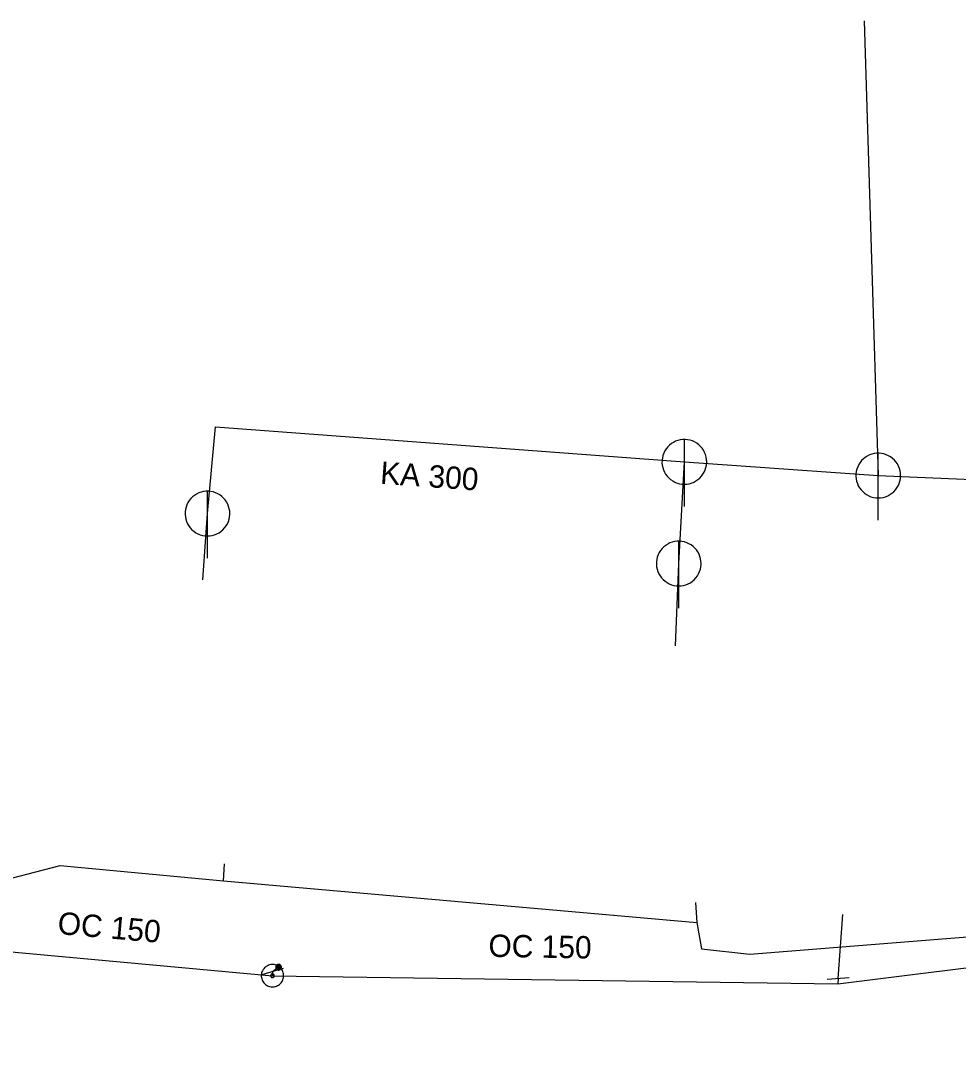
# Model space of a CAD drawing. Extents: x -759784 to -759434, y -974861 to -974639.
# Drawn here: x -759531.42 to -759489.52, y -974742.26 to -974695.97 of the extents above; entities that cross this region are included whole.
import ezdxf

# ---------------------------------------------------------------- set-up
doc = ezdxf.new("R2010")
doc.units = 0
for name, color, linetype in [('IS_CETIN_sdělovací kabel_podzemní', 7, 'Continuous'), ('IS_popis_ScVK', 7, 'Continuous'), ('IS_ScVK_Kanal', 7, 'Continuous'), ('IS_ScVK_Vodovod', 7, 'Continuous')]:
    doc.layers.add(name, color=color, linetype=linetype)

msp = doc.modelspace()

# ---------------------------------------------------------------- linework, layer by layer
at = {"layer": 'IS_CETIN_sdělovací kabel_podzemní'}
for points in [[(-759544.45, -974733.8), (-759533, -974734.6), (-759529.66, -974733.73), (-759522.36, -974734.42)], [(-759522.36, -974734.42), (-759522.31, -974733.66)], [(-759522.36, -974734.42), (-759501.2, -974736.28)], [(-759501.27, -974735.38), (-759501.2, -974736.28)], [(-759501.2, -974736.28), (-759500.99, -974737.45), (-759498.83, -974737.7), (-759486.31, -974736.7), (-759484.66, -974737.9), (-759478.97, -974736.71), (-759474.26, -974737.04), (-759472.35, -974737.88), (-759470.97, -974738.53), (-759469.61, -974739.15), (-759466.38, -974739.73), (-759464.12, -974740.75), (-759461.22, -974742.26)]]:
    msp.add_lwpolyline(points, dxfattribs=at)
at = {"layer": 'IS_ScVK_Kanal'}
for points in [[(-759493.728, -974695.967), (-759493.097, -974716.3)], [(-759523.077, -974718), (-759522.715, -974714.129)], [(-759522.715, -974714.129), (-759501.763, -974715.688)], [(-759500.763, -974715.688), (-759500.768, -974715.579), (-759500.786, -974715.471), (-759500.816, -974715.365), (-759500.856, -974715.264), (-759500.908, -974715.167), (-759500.97, -974715.077), (-759501.042, -974714.994), (-759501.122, -974714.92), (-759501.21, -974714.854), (-759501.304, -974714.799), (-759501.404, -974714.754), (-759501.509, -974714.721), (-759501.616, -974714.699), (-759501.725, -974714.689), (-759501.835, -974714.691), (-759501.943, -974714.705), (-759502.05, -974714.73), (-759502.153, -974714.767), (-759502.251, -974714.816), (-759502.343, -974714.874), (-759502.429, -974714.943), (-759502.506, -974715.02), (-759502.575, -974715.106), (-759502.634, -974715.198), (-759502.682, -974715.296), (-759502.719, -974715.399), (-759502.745, -974715.506), (-759502.759, -974715.614), (-759502.762, -974715.724), (-759502.752, -974715.833), (-759502.731, -974715.94), (-759502.697, -974716.044), (-759502.653, -974716.144), (-759502.598, -974716.239), (-759502.532, -974716.327), (-759502.458, -974716.407), (-759502.375, -974716.479), (-759502.285, -974716.541), (-759502.189, -974716.593), (-759502.087, -974716.634), (-759501.982, -974716.664), (-759501.874, -974716.682), (-759501.764, -974716.688), (-759501.655, -974716.682), (-759501.547, -974716.664), (-759501.442, -974716.635), (-759501.34, -974716.594), (-759501.243, -974716.542), (-759501.153, -974716.48), (-759501.07, -974716.409), (-759500.995, -974716.329), (-759500.93, -974716.241), (-759500.874, -974716.147), (-759500.83, -974716.047), (-759500.796, -974715.943), (-759500.774, -974715.835), (-759500.764, -974715.726), (-759500.763, -974715.688)], [(-759501.763, -974717.688), (-759501.762, -974714.688)], [(-759492.097, -974716.3), (-759492.102, -974716.191), (-759492.12, -974716.083), (-759492.15, -974715.977), (-759492.19, -974715.876), (-759492.242, -974715.779), (-759492.304, -974715.689), (-759492.376, -974715.606), (-759492.456, -974715.532), (-759492.544, -974715.466), (-759492.638, -974715.411), (-759492.738, -974715.366), (-759492.843, -974715.333), (-759492.95, -974715.311), (-759493.059, -974715.301), (-759493.169, -974715.303), (-759493.277, -974715.317), (-759493.384, -974715.342), (-759493.487, -974715.379), (-759493.585, -974715.428), (-759493.677, -974715.486), (-759493.763, -974715.555), (-759493.84, -974715.632), (-759493.909, -974715.718), (-759493.968, -974715.81), (-759494.016, -974715.908), (-759494.053, -974716.011), (-759494.079, -974716.118), (-759494.093, -974716.226), (-759494.096, -974716.336), (-759494.086, -974716.445), (-759494.065, -974716.552), (-759494.031, -974716.656), (-759493.987, -974716.756), (-759493.932, -974716.851), (-759493.866, -974716.939), (-759493.792, -974717.019), (-759493.709, -974717.091), (-759493.619, -974717.153), (-759493.523, -974717.205), (-759493.421, -974717.246), (-759493.316, -974717.276), (-759493.208, -974717.294), (-759493.098, -974717.3), (-759492.989, -974717.294), (-759492.881, -974717.276), (-759492.776, -974717.247), (-759492.674, -974717.206), (-759492.577, -974717.154), (-759492.487, -974717.092), (-759492.404, -974717.021), (-759492.329, -974716.941), (-759492.264, -974716.853), (-759492.208, -974716.759), (-759492.164, -974716.659), (-759492.13, -974716.555), (-759492.108, -974716.447), (-759492.098, -974716.338), (-759492.097, -974716.3)], [(-759493.097, -974718.3), (-759493.096, -974715.3)], [(-759502.016, -974720.235), (-759501.763, -974715.688)], [(-759501.763, -974715.688), (-759493.097, -974716.3)], [(-759493.097, -974716.3), (-759477.359, -974716.961)], [(-759522.077, -974718), (-759522.082, -974717.891), (-759522.1, -974717.783), (-759522.13, -974717.677), (-759522.17, -974717.576), (-759522.222, -974717.479), (-759522.284, -974717.389), (-759522.356, -974717.306), (-759522.436, -974717.232), (-759522.524, -974717.166), (-759522.618, -974717.111), (-759522.718, -974717.066), (-759522.823, -974717.033), (-759522.93, -974717.011), (-759523.039, -974717.001), (-759523.149, -974717.003), (-759523.257, -974717.017), (-759523.364, -974717.042), (-759523.467, -974717.079), (-759523.565, -974717.128), (-759523.657, -974717.186), (-759523.743, -974717.255), (-759523.82, -974717.332), (-759523.889, -974717.418), (-759523.948, -974717.51), (-759523.996, -974717.608), (-759524.033, -974717.711), (-759524.059, -974717.818), (-759524.073, -974717.926), (-759524.076, -974718.036), (-759524.066, -974718.145), (-759524.045, -974718.252), (-759524.011, -974718.356), (-759523.967, -974718.456), (-759523.912, -974718.551), (-759523.846, -974718.639), (-759523.772, -974718.719), (-759523.689, -974718.791), (-759523.599, -974718.853), (-759523.503, -974718.905), (-759523.401, -974718.946), (-759523.296, -974718.976), (-759523.188, -974718.994), (-759523.078, -974719), (-759522.969, -974718.994), (-759522.861, -974718.976), (-759522.756, -974718.947), (-759522.654, -974718.906), (-759522.557, -974718.854), (-759522.467, -974718.792), (-759522.384, -974718.721), (-759522.309, -974718.641), (-759522.244, -974718.553), (-759522.188, -974718.459), (-759522.144, -974718.359), (-759522.11, -974718.255), (-759522.088, -974718.147), (-759522.078, -974718.038), (-759522.077, -974718)], [(-759523.077, -974720), (-759523.076, -974717)], [(-759523.28, -974720.963), (-759523.077, -974718)], [(-759501.015, -974720.234), (-759501.02, -974720.125), (-759501.038, -974720.017), (-759501.068, -974719.911), (-759501.108, -974719.81), (-759501.16, -974719.713), (-759501.222, -974719.623), (-759501.294, -974719.54), (-759501.374, -974719.466), (-759501.462, -974719.4), (-759501.556, -974719.345), (-759501.656, -974719.3), (-759501.761, -974719.267), (-759501.868, -974719.245), (-759501.977, -974719.235), (-759502.087, -974719.237), (-759502.195, -974719.251), (-759502.302, -974719.276), (-759502.405, -974719.313), (-759502.503, -974719.362), (-759502.595, -974719.42), (-759502.681, -974719.489), (-759502.758, -974719.566), (-759502.827, -974719.652), (-759502.886, -974719.744), (-759502.934, -974719.842), (-759502.971, -974719.945), (-759502.997, -974720.052), (-759503.011, -974720.16), (-759503.014, -974720.27), (-759503.004, -974720.379), (-759502.983, -974720.486), (-759502.949, -974720.59), (-759502.905, -974720.69), (-759502.85, -974720.785), (-759502.784, -974720.873), (-759502.71, -974720.953), (-759502.627, -974721.025), (-759502.537, -974721.087), (-759502.441, -974721.139), (-759502.339, -974721.18), (-759502.234, -974721.21), (-759502.126, -974721.228), (-759502.016, -974721.234), (-759501.907, -974721.228), (-759501.799, -974721.21), (-759501.694, -974721.181), (-759501.592, -974721.14), (-759501.495, -974721.088), (-759501.405, -974721.026), (-759501.322, -974720.955), (-759501.247, -974720.875), (-759501.182, -974720.787), (-759501.126, -974720.693), (-759501.082, -974720.593), (-759501.048, -974720.489), (-759501.026, -974720.381), (-759501.016, -974720.272), (-759501.015, -974720.234)], [(-759502.015, -974722.234), (-759502.014, -974719.234)], [(-759502.163, -974723.919), (-759502.016, -974720.235)], [(-759519.899, -974738.278), (-759520.168, -974738.478)], [(-759520.168, -974738.478), (-759520.172, -974738.658)], [(-759494.888, -974738.788), (-759494.905, -974739.024)]]:
    msp.add_lwpolyline(points, dxfattribs=at)
at = {"layer": 'IS_ScVK_Vodovod'}
for points in [[(-759494.888, -974738.788), (-759494.686, -974735.919)], [(-759520.172, -974738.658), (-759494.905, -974739.024), (-759476.881, -974736.765), (-759471.711, -974737.208)], [(-759533.638, -974737.429), (-759520.172, -974738.658)], [(-759519.672, -974738.681), (-759519.673, -974738.629), (-759519.678, -974738.577), (-759519.69, -974738.526), (-759519.705, -974738.476), (-759519.727, -974738.428), (-759519.754, -974738.383), (-759519.785, -974738.341), (-759519.82, -974738.303), (-759519.859, -974738.268), (-759519.901, -974738.237), (-759519.947, -974738.211), (-759519.995, -974738.19), (-759520.044, -974738.174), (-759520.096, -974738.164), (-759520.148, -974738.158), (-759520.2, -974738.159), (-759520.252, -974738.164), (-759520.304, -974738.176), (-759520.353, -974738.191), (-759520.401, -974738.213), (-759520.446, -974738.24), (-759520.489, -974738.271), (-759520.527, -974738.306), (-759520.562, -974738.345), (-759520.592, -974738.387), (-759520.618, -974738.433), (-759520.64, -974738.481), (-759520.655, -974738.53), (-759520.665, -974738.582), (-759520.671, -974738.634), (-759520.67, -974738.686), (-759520.665, -974738.738), (-759520.654, -974738.79), (-759520.638, -974738.839), (-759520.616, -974738.887), (-759520.59, -974738.932), (-759520.559, -974738.975), (-759520.524, -974739.013), (-759520.484, -974739.048), (-759520.442, -974739.078), (-759520.396, -974739.104), (-759520.349, -974739.126), (-759520.299, -974739.141), (-759520.247, -974739.151), (-759520.195, -974739.157), (-759520.143, -974739.156), (-759520.091, -974739.151), (-759520.04, -974739.14), (-759519.99, -974739.124), (-759519.942, -974739.102), (-759519.897, -974739.076), (-759519.855, -974739.045), (-759519.817, -974739.01), (-759519.782, -974738.97), (-759519.751, -974738.928), (-759519.725, -974738.882), (-759519.704, -974738.835), (-759519.688, -974738.785), (-759519.678, -974738.733), (-759519.672, -974738.681)], [(-759519.688, -974738.336), (-759520.647, -974738.618)], [(-759520.025, -974738.278), (-759520.025, -974738.291), (-759520.022, -974738.304), (-759520.02, -974738.317), (-759520.015, -974738.329), (-759520.009, -974738.341), (-759520.002, -974738.352), (-759519.994, -974738.362), (-759519.983, -974738.372), (-759519.973, -974738.38), (-759519.963, -974738.387), (-759519.951, -974738.393), (-759519.939, -974738.398), (-759519.926, -974738.401), (-759519.913, -974738.403), (-759519.9, -974738.405), (-759519.887, -974738.404), (-759519.874, -974738.402), (-759519.861, -974738.399), (-759519.848, -974738.394), (-759519.837, -974738.388), (-759519.826, -974738.381), (-759519.816, -974738.373), (-759519.806, -974738.363), (-759519.798, -974738.353), (-759519.791, -974738.342), (-759519.785, -974738.33), (-759519.78, -974738.318), (-759519.777, -974738.305), (-759519.775, -974738.292), (-759519.772, -974738.279), (-759519.774, -974738.266), (-759519.776, -974738.253), (-759519.779, -974738.24), (-759519.784, -974738.228), (-759519.789, -974738.216), (-759519.797, -974738.205), (-759519.804, -974738.195), (-759519.815, -974738.185), (-759519.825, -974738.177), (-759519.836, -974738.17), (-759519.848, -974738.164), (-759519.86, -974738.159), (-759519.873, -974738.156), (-759519.886, -974738.154), (-759519.899, -974738.153), (-759519.912, -974738.153), (-759519.924, -974738.155), (-759519.938, -974738.158), (-759519.95, -974738.163), (-759519.962, -974738.169), (-759519.973, -974738.176), (-759519.983, -974738.184), (-759519.993, -974738.194), (-759520, -974738.204), (-759520.008, -974738.215), (-759520.014, -974738.227), (-759520.019, -974738.239), (-759520.022, -974738.252), (-759520.024, -974738.265), (-759520.025, -974738.278)], [(-759520.005, -974738.278), (-759520.005, -974738.289), (-759520.004, -974738.3), (-759520, -974738.311), (-759519.997, -974738.321), (-759519.992, -974738.331), (-759519.986, -974738.34), (-759519.978, -974738.349), (-759519.971, -974738.357), (-759519.962, -974738.364), (-759519.953, -974738.37), (-759519.943, -974738.375), (-759519.933, -974738.379), (-759519.922, -974738.382), (-759519.911, -974738.385), (-759519.9, -974738.385), (-759519.889, -974738.385), (-759519.878, -974738.383), (-759519.867, -974738.38), (-759519.857, -974738.376), (-759519.847, -974738.371), (-759519.838, -974738.365), (-759519.829, -974738.358), (-759519.821, -974738.35), (-759519.814, -974738.341), (-759519.808, -974738.332), (-759519.803, -974738.322), (-759519.799, -974738.312), (-759519.796, -974738.301), (-759519.794, -974738.29), (-759519.793, -974738.279), (-759519.793, -974738.268), (-759519.794, -974738.257), (-759519.798, -974738.246), (-759519.802, -974738.236), (-759519.807, -974738.226), (-759519.813, -974738.217), (-759519.82, -974738.208), (-759519.828, -974738.2), (-759519.837, -974738.193), (-759519.846, -974738.187), (-759519.856, -974738.182), (-759519.865, -974738.178), (-759519.877, -974738.175), (-759519.887, -974738.173), (-759519.899, -974738.173), (-759519.91, -974738.172), (-759519.921, -974738.174), (-759519.932, -974738.177), (-759519.941, -974738.181), (-759519.951, -974738.186), (-759519.961, -974738.192), (-759519.97, -974738.199), (-759519.978, -974738.207), (-759519.985, -974738.216), (-759519.99, -974738.225), (-759519.995, -974738.235), (-759520, -974738.245), (-759520.003, -974738.256), (-759520.005, -974738.267), (-759520.005, -974738.278)], [(-759519.986, -974738.278), (-759519.986, -974738.287), (-759519.985, -974738.296), (-759519.982, -974738.305), (-759519.978, -974738.313), (-759519.975, -974738.321), (-759519.97, -974738.329), (-759519.963, -974738.336), (-759519.958, -974738.342), (-759519.951, -974738.348), (-759519.943, -974738.353), (-759519.934, -974738.357), (-759519.927, -974738.36), (-759519.918, -974738.363), (-759519.909, -974738.364), (-759519.9, -974738.366), (-759519.891, -974738.365), (-759519.882, -974738.364), (-759519.873, -974738.361), (-759519.865, -974738.358), (-759519.857, -974738.354), (-759519.848, -974738.349), (-759519.842, -974738.343), (-759519.836, -974738.337), (-759519.83, -974738.33), (-759519.825, -974738.322), (-759519.821, -974738.314), (-759519.818, -974738.306), (-759519.815, -974738.297), (-759519.814, -974738.288), (-759519.811, -974738.279), (-759519.813, -974738.27), (-759519.814, -974738.261), (-759519.816, -974738.252), (-759519.82, -974738.244), (-759519.824, -974738.236), (-759519.829, -974738.228), (-759519.835, -974738.221), (-759519.841, -974738.215), (-759519.848, -974738.209), (-759519.856, -974738.204), (-759519.864, -974738.2), (-759519.872, -974738.197), (-759519.88, -974738.194), (-759519.89, -974738.193), (-759519.899, -974738.192), (-759519.907, -974738.192), (-759519.917, -974738.193), (-759519.926, -974738.196), (-759519.934, -974738.199), (-759519.941, -974738.203), (-759519.95, -974738.208), (-759519.956, -974738.214), (-759519.963, -974738.22), (-759519.968, -974738.227), (-759519.973, -974738.235), (-759519.978, -974738.243), (-759519.981, -974738.251), (-759519.983, -974738.26), (-759519.985, -974738.269), (-759519.986, -974738.278)], [(-759519.966, -974738.278), (-759519.966, -974738.285), (-759519.965, -974738.292), (-759519.963, -974738.299), (-759519.961, -974738.305), (-759519.958, -974738.311), (-759519.954, -974738.317), (-759519.95, -974738.323), (-759519.945, -974738.328), (-759519.939, -974738.332), (-759519.933, -974738.336), (-759519.927, -974738.339), (-759519.921, -974738.342), (-759519.914, -974738.343), (-759519.907, -974738.346), (-759519.9, -974738.346), (-759519.892, -974738.346), (-759519.886, -974738.344), (-759519.879, -974738.343), (-759519.873, -974738.34), (-759519.865, -974738.337), (-759519.861, -974738.333), (-759519.855, -974738.329), (-759519.85, -974738.324), (-759519.846, -974738.318), (-759519.842, -974738.312), (-759519.838, -974738.306), (-759519.836, -974738.3), (-759519.834, -974738.293), (-759519.833, -974738.286), (-759519.831, -974738.279), (-759519.831, -974738.272), (-759519.833, -974738.265), (-759519.835, -974738.258), (-759519.838, -974738.252), (-759519.841, -974738.245), (-759519.845, -974738.24), (-759519.848, -974738.234), (-759519.853, -974738.229), (-759519.86, -974738.225), (-759519.865, -974738.221), (-759519.872, -974738.218), (-759519.878, -974738.215), (-759519.885, -974738.213), (-759519.892, -974738.212), (-759519.899, -974738.212), (-759519.906, -974738.212), (-759519.913, -974738.212), (-759519.919, -974738.214), (-759519.926, -974738.217), (-759519.932, -974738.22), (-759519.938, -974738.224), (-759519.944, -974738.228), (-759519.949, -974738.233), (-759519.953, -974738.239), (-759519.956, -974738.244), (-759519.96, -974738.251), (-759519.963, -974738.257), (-759519.963, -974738.264), (-759519.966, -974738.271), (-759519.966, -974738.278)], [(-759519.946, -974738.278), (-759519.946, -974738.283), (-759519.946, -974738.288), (-759519.945, -974738.293), (-759519.943, -974738.297), (-759519.941, -974738.302), (-759519.938, -974738.306), (-759519.934, -974738.309), (-759519.931, -974738.313), (-759519.928, -974738.316), (-759519.924, -974738.319), (-759519.919, -974738.321), (-759519.914, -974738.323), (-759519.91, -974738.324), (-759519.905, -974738.326), (-759519.9, -974738.326), (-759519.895, -974738.326), (-759519.89, -974738.325), (-759519.885, -974738.324), (-759519.88, -974738.322), (-759519.875, -974738.32), (-759519.872, -974738.317), (-759519.868, -974738.314), (-759519.865, -974738.31), (-759519.862, -974738.307), (-759519.858, -974738.303), (-759519.857, -974738.298), (-759519.855, -974738.294), (-759519.853, -974738.289), (-759519.853, -974738.284), (-759519.852, -974738.279), (-759519.852, -974738.274), (-759519.853, -974738.269), (-759519.853, -974738.264), (-759519.856, -974738.26), (-759519.858, -974738.255), (-759519.861, -974738.251), (-759519.864, -974738.247), (-759519.867, -974738.244), (-759519.87, -974738.241), (-759519.875, -974738.238), (-759519.88, -974738.236), (-759519.884, -974738.234), (-759519.889, -974738.233), (-759519.894, -974738.232), (-759519.899, -974738.232), (-759519.904, -974738.232), (-759519.909, -974738.233), (-759519.914, -974738.233), (-759519.918, -974738.235), (-759519.923, -974738.237), (-759519.927, -974738.24), (-759519.929, -974738.243), (-759519.934, -974738.246), (-759519.936, -974738.25), (-759519.94, -974738.254), (-759519.941, -974738.259), (-759519.944, -974738.263), (-759519.945, -974738.268), (-759519.946, -974738.273), (-759519.946, -974738.278)], [(-759519.926, -974738.278), (-759519.926, -974738.281), (-759519.927, -974738.284), (-759519.926, -974738.286), (-759519.924, -974738.289), (-759519.924, -974738.292), (-759519.922, -974738.294), (-759519.919, -974738.296), (-759519.918, -974738.298), (-759519.916, -974738.3), (-759519.914, -974738.302), (-759519.911, -974738.304), (-759519.907, -974738.305), (-759519.906, -974738.305), (-759519.902, -974738.306), (-759519.9, -974738.306), (-759519.897, -974738.306), (-759519.894, -974738.306), (-759519.891, -974738.305), (-759519.889, -974738.304), (-759519.886, -974738.303), (-759519.884, -974738.301), (-759519.88, -974738.299), (-759519.879, -974738.297), (-759519.878, -974738.295), (-759519.875, -974738.293), (-759519.875, -974738.29), (-759519.873, -974738.287), (-759519.873, -974738.285), (-759519.872, -974738.282), (-759519.87, -974738.279), (-759519.872, -974738.276), (-759519.872, -974738.273), (-759519.873, -974738.27), (-759519.874, -974738.268), (-759519.875, -974738.265), (-759519.877, -974738.263), (-759519.878, -974738.26), (-759519.88, -974738.258), (-759519.883, -974738.257), (-759519.885, -974738.255), (-759519.887, -974738.254), (-759519.89, -974738.253), (-759519.892, -974738.252), (-759519.896, -974738.252), (-759519.899, -974738.251), (-759519.902, -974738.252), (-759519.905, -974738.251), (-759519.907, -974738.253), (-759519.91, -974738.253), (-759519.913, -974738.254), (-759519.914, -974738.256), (-759519.917, -974738.257), (-759519.919, -974738.259), (-759519.921, -974738.262), (-759519.923, -974738.264), (-759519.924, -974738.267), (-759519.924, -974738.269), (-759519.926, -974738.272), (-759519.926, -974738.275), (-759519.926, -974738.278)], [(-759519.907, -974738.278), (-759519.907, -974738.28), (-759519.907, -974738.28), (-759519.906, -974738.28), (-759519.906, -974738.282), (-759519.907, -974738.283), (-759519.905, -974738.283), (-759519.905, -974738.283), (-759519.905, -974738.285), (-759519.905, -974738.285), (-759519.904, -974738.286), (-759519.902, -974738.286), (-759519.902, -974738.286), (-759519.902, -974738.287), (-759519.9, -974738.287), (-759519.9, -974738.287), (-759519.899, -974738.287), (-759519.897, -974738.287), (-759519.897, -974738.286), (-759519.897, -974738.286), (-759519.895, -974738.286), (-759519.895, -974738.285), (-759519.895, -974738.285), (-759519.894, -974738.284), (-759519.894, -974738.284), (-759519.892, -974738.283), (-759519.892, -974738.282), (-759519.891, -974738.281), (-759519.891, -974738.281), (-759519.891, -974738.28), (-759519.891, -974738.279), (-759519.891, -974738.278), (-759519.891, -974738.277), (-759519.891, -974738.277), (-759519.892, -974738.276), (-759519.892, -974738.275), (-759519.892, -974738.274), (-759519.892, -974738.274), (-759519.894, -974738.273), (-759519.894, -974738.273), (-759519.895, -974738.272), (-759519.896, -974738.272), (-759519.897, -974738.271), (-759519.897, -974738.271), (-759519.897, -974738.271), (-759519.899, -974738.271), (-759519.9, -974738.271), (-759519.901, -974738.271), (-759519.901, -974738.271), (-759519.902, -974738.272), (-759519.902, -974738.271), (-759519.904, -974738.273), (-759519.904, -974738.273), (-759519.905, -974738.273), (-759519.905, -974738.273), (-759519.906, -974738.275), (-759519.906, -974738.276), (-759519.906, -974738.277), (-759519.907, -974738.277), (-759519.907, -974738.278), (-759519.907, -974738.278)], [(-759520.09, -974738.661), (-759520.089, -974738.652), (-759520.091, -974738.644), (-759520.092, -974738.636), (-759520.095, -974738.628), (-759520.099, -974738.62), (-759520.103, -974738.613), (-759520.108, -974738.605), (-759520.114, -974738.599), (-759520.12, -974738.594), (-759520.127, -974738.589), (-759520.135, -974738.584), (-759520.143, -974738.581), (-759520.151, -974738.578), (-759520.159, -974738.576), (-759520.168, -974738.576), (-759520.177, -974738.575), (-759520.185, -974738.577), (-759520.193, -974738.578), (-759520.201, -974738.581), (-759520.209, -974738.585), (-759520.216, -974738.589), (-759520.224, -974738.594), (-759520.23, -974738.6), (-759520.236, -974738.606), (-759520.24, -974738.613), (-759520.245, -974738.621), (-759520.248, -974738.629), (-759520.251, -974738.637), (-759520.253, -974738.645), (-759520.253, -974738.654), (-759520.254, -974738.663), (-759520.252, -974738.671), (-759520.251, -974738.679), (-759520.248, -974738.687), (-759520.244, -974738.695), (-759520.241, -974738.702), (-759520.235, -974738.71), (-759520.229, -974738.716), (-759520.223, -974738.722), (-759520.216, -974738.726), (-759520.208, -974738.731), (-759520.2, -974738.734), (-759520.192, -974738.737), (-759520.184, -974738.739), (-759520.175, -974738.739), (-759520.166, -974738.74), (-759520.158, -974738.738), (-759520.15, -974738.737), (-759520.142, -974738.734), (-759520.134, -974738.73), (-759520.127, -974738.727), (-759520.119, -974738.721), (-759520.113, -974738.715), (-759520.108, -974738.709), (-759520.103, -974738.702), (-759520.098, -974738.694), (-759520.095, -974738.686), (-759520.092, -974738.678), (-759520.09, -974738.67), (-759520.09, -974738.661)], [(-759494.389, -974738.749), (-759495.386, -974738.825)]]:
    msp.add_lwpolyline(points, dxfattribs=at)

# ---------------------------------------------------------------- texts
at = {"layer": 'IS_popis_ScVK'}
for s, rotation, p in [('KA 300', 356, (-759515.377, -974716.666)), ('OC 150', 355, (-759529.803, -974736.79)), ('OC 150', 359, (-759510.524, -974737.812))]:
    msp.add_text(s, height=1, rotation=rotation, dxfattribs=at).set_placement(p)

doc.saveas('drawing.dxf')
